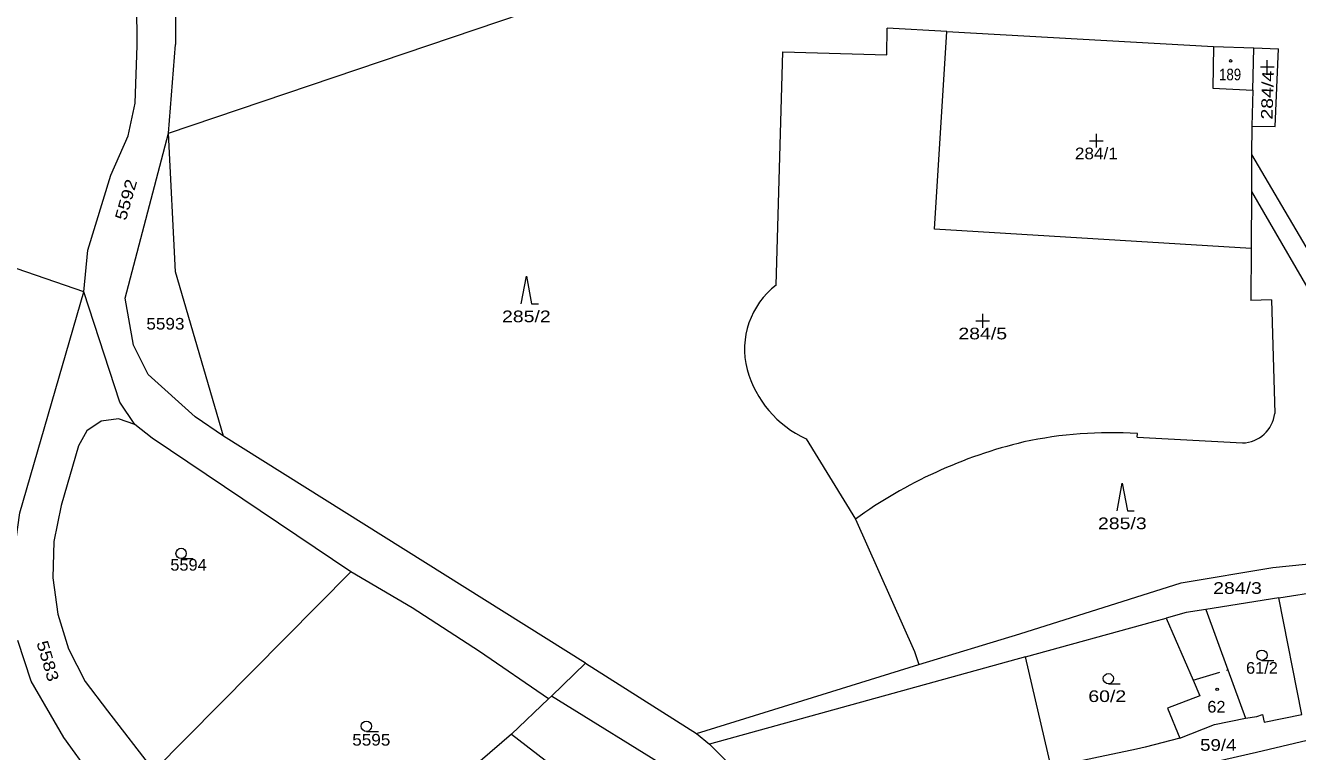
# Model space of a CAD drawing. Extents: x -590528 to -586543, y -1119609 to -1116685.
# Drawn here: x -589346.9 to -589161.2, y -1118438.6 to -1118332.6 of the extents above; entities that cross this region are included whole.
import ezdxf
from ezdxf.enums import TextEntityAlignment as Align

# ---------------------------------------------------------------- set-up
doc = ezdxf.new("R2010")
doc.units = 0
doc.header["$LTSCALE"] = 0.68
doc.linetypes.add('LONG_DASHED', pattern=[7.5, 6, -1.5])
for name, color, linetype, lineweight in [('1', 7, 'Continuous', 13), ('2', 7, 'LONG_DASHED', 13), ('3', 7, 'Continuous', 13), ('6', 7, 'Continuous', 13)]:
    doc.layers.add(name, color=color, linetype=linetype, lineweight=lineweight)

msp = doc.modelspace()

# ---------------------------------------------------------------- linework, layer by layer
at = {"layer": '1'}
for p, q in [((-589326.04, -1118348.34), (-589245.69, -1118321.18)), ((-589221.18, -1118336.9), (-589221.12, -1118333.05)), ((-589212.42, -1118333.53), (-589221.12, -1118333.05)), ((-589212.42, -1118333.53), (-589173.46, -1118335.7)), ((-589326.04, -1118348.34), (-589325.05, -1118335.4)), ((-589237.33, -1118370.53), (-589236.34, -1118336.48)), ((-589236.34, -1118336.48), (-589221.18, -1118336.9)), ((-589173.46, -1118335.7), (-589173.55, -1118341.78)), ((-589167.7, -1118342.06), (-589167.58, -1118335.91)), ((-589173.55, -1118341.78), (-589167.7, -1118342.06)), ((-589167.7, -1118342.06), (-589167.88, -1118347.35)), ((-589338.39, -1118371.5), (-589403.04, -1118349.36)), ((-589332.36, -1118372.41), (-589326.04, -1118348.34)), ((-589325.03, -1118368.61), (-589326.04, -1118348.34)), ((-589167.9, -1118351.48), (-589148.72, -1118384.16)), ((-589167.93, -1118356.86), (-589150.27, -1118387.26)), ((-589318.03, -1118392.58), (-589325.03, -1118368.61)), ((-589165.02, -1118372.65), (-589168.02, -1118372.79)), ((-589165.02, -1118372.65), (-589164.53, -1118389.24)), ((-589318.03, -1118392.58), (-589322.16, -1118389.75)), ((-589184.6, -1118392.69), (-589184.58, -1118392.17)), ((-589299.45, -1118412.34), (-589328.45, -1118392.88)), ((-589265.17, -1118425.71), (-589318.03, -1118392.58)), ((-589184.6, -1118392.69), (-589169.25, -1118393.56)), ((-589328.21, -1118441.4), (-589299.45, -1118412.34)), ((-589200.94, -1118424.78), (-589182.2, -1118419.61)), ((-589182.2, -1118419.61), (-589180.39, -1118419.11)), ((-589216.49, -1118425.91), (-589201.73, -1118421.4)), ((-589270.59, -1118430.92), (-589280.62, -1118423.97)), ((-589217.13, -1118423.98), (-589216.49, -1118425.91)), ((-589270.14, -1118430.49), (-589265.17, -1118425.71)), ((-589265.17, -1118425.71), (-589248.97, -1118435.94)), ((-589248.97, -1118435.94), (-589216.49, -1118425.91)), ((-589200.94, -1118424.78), (-589247.08, -1118437.51)), ((-589197.19, -1118440.86), (-589200.94, -1118424.78)), ((-589275.98, -1118436.06), (-589270.59, -1118430.92)), ((-589270.59, -1118430.92), (-589270.14, -1118430.49)), ((-589251.89, -1118441.81), (-589270.14, -1118430.49)), ((-589275.98, -1118436.06), (-589292.08, -1118449.9)), ((-589248.97, -1118435.94), (-589247.08, -1118437.51))]:
    msp.add_line(p, q, dxfattribs=at)
for points in [[(-589324.34, -1118242.06), (-589284.26, -1118252.28), (-589283.44, -1118293.46), (-589306.78, -1118295.36), (-589324.77, -1118296.83), (-589324.8, -1118300.73), (-589324.91, -1118315.62), (-589325.05, -1118335.4)], [(-589338.39, -1118371.5), (-589337.84, -1118365.42), (-589334.45, -1118354.46), (-589331.95, -1118348.76), (-589330.94, -1118343.98), (-589330.65, -1118335.55), (-589330.68, -1118329.38)], [(-589167.98, -1118365.19), (-589214.19, -1118362.36), (-589212.42, -1118333.53)], [(-589173.46, -1118335.7), (-589167.58, -1118335.91), (-589163.96, -1118336.03)], [(-589167.88, -1118347.35), (-589164.44, -1118347.37), (-589163.96, -1118336.03)], [(-589167.88, -1118347.35), (-589167.9, -1118351.48), (-589167.93, -1118356.86), (-589167.98, -1118365.19), (-589168.02, -1118372.79)], [(-589382.59, -1118398.58), (-589371.5, -1118401.89), (-589356.23, -1118406.75), (-589348.52, -1118409.33), (-589347.77, -1118403.74), (-589338.39, -1118371.5)], [(-589330.98, -1118390.87), (-589333.18, -1118387.62), (-589338.39, -1118371.5)], [(-589322.16, -1118389.75), (-589329.04, -1118383.57), (-589331.18, -1118379.27), (-589332.36, -1118372.41)], [(-589328.45, -1118392.88), (-589330.98, -1118390.87), (-589333.36, -1118390.04), (-589335.87, -1118390.37), (-589337.96, -1118391.78), (-589339.21, -1118393.98), (-589341.74, -1118402.69), (-589342.79, -1118407.92), (-589342.96, -1118413.25), (-589342.23, -1118418.53), (-589340.63, -1118423.61)], [(-589232.96, -1118392.96), (-589225.76, -1118404.68), (-589217.13, -1118423.98)], [(-589374.32, -1118404.86), (-589380.45, -1118462.92), (-589374.76, -1118462.64), (-589367.9, -1118459.92), (-589356.04, -1118453.27), (-589344.63, -1118446.86), (-589337.38, -1118442.01), (-589341.33, -1118436.52), (-589346.1, -1118428.33), (-589348.05, -1118422.4)], [(-589201.73, -1118421.4), (-589178.17, -1118413.95), (-589164.81, -1118411.74), (-589141.45, -1118409.35)], [(-589280.62, -1118423.97), (-589290.49, -1118417.6), (-589299.45, -1118412.34)], [(-589163.94, -1118416.17), (-589174.61, -1118417.86), (-589177.47, -1118418.31), (-589180.39, -1118419.11)], [(-589178.39, -1118436.62), (-589173.34, -1118434.64), (-589168.8, -1118433.71), (-589167.16, -1118433.45), (-589166.32, -1118433.19), (-589166.08, -1118434.28), (-589160.56, -1118433.2), (-589163.94, -1118416.17)], [(-589163.94, -1118416.17), (-589157.76, -1118415.19), (-589148.57, -1118424.88)], [(-589174.61, -1118417.86), (-589171.39, -1118426.64), (-589168.8, -1118433.71)], [(-589180.39, -1118419.11), (-589176.44, -1118428.18), (-589175.45, -1118430.45), (-589180.19, -1118432.28), (-589178.39, -1118436.62), (-589183.44, -1118437.97), (-589184.7, -1118438.23), (-589197.19, -1118440.86)], [(-589340.63, -1118423.61), (-589338.2, -1118428.36), (-589334.98, -1118432.65), (-589328.21, -1118441.4), (-589325.78, -1118444.54), (-589322.29, -1118448.62)], [(-589199.68, -1118448.07), (-589194.46, -1118445.28), (-589188.61, -1118443.7), (-589176.77, -1118440.88), (-589167.18, -1118438.67), (-589159.81, -1118436.94), (-589154.47, -1118435.78), (-589147.85, -1118434.23), (-589145.26, -1118446.55), (-589151.66, -1118448.03), (-589156.96, -1118449.29), (-589164.32, -1118451), (-589166.12, -1118451.49)], [(-589275.98, -1118436.06), (-589265.05, -1118444.46), (-589262.78, -1118446.21)], [(-589247.08, -1118437.51), (-589221.83, -1118462.82), (-589205.62, -1118461.09)]]:
    msp.add_lwpolyline(points, dxfattribs=at)
for centre, radius, start, end in [((-589230.1545, -1118379.8912), 11.795, 127.47081, 194.37743), ((-589226.2424, -1118378.5155), 15.9301, 195.67687, 245.05876), ((-589169.3468, -1118388.7157), 4.8452, 271.14464, 353.78824), ((-589188.3272, -1118453.7384), 61.6824, 86.51712, 102.02686), ((-589184.8908, -1118461.3765), 69.8912, 103.47757, 125.78561)]:
    msp.add_arc(centre, radius, start, end, dxfattribs=at)
at = {"layer": '2'}
msp.add_line((-589176.44, -1118428.18), (-589171.39, -1118426.64), dxfattribs=at)
at = {"layer": '6'}
for p, q in [((-589165.62, -1118339.69), (-589165.62, -1118337.69)), ((-589166.62, -1118338.69), (-589164.62, -1118338.69)), ((-589191.57, -1118349.46), (-589189.57, -1118349.46)), ((-589190.57, -1118350.46), (-589190.57, -1118348.46)), ((-589208.16, -1118375.74), (-589206.16, -1118375.74)), ((-589207.16, -1118376.74), (-589207.16, -1118374.74)), ((-589324.21, -1118410.42), (-589322.46, -1118410.42)), ((-589166.39, -1118425.28), (-589164.64, -1118425.28)), ((-589188.82, -1118428.7), (-589187.07, -1118428.7)), ((-589297.16, -1118435.65), (-589295.41, -1118435.65))]:
    msp.add_line(p, q, dxfattribs=at)
for points in [[(-589274.55, -1118373.24), (-589273.8, -1118369.24), (-589273.05, -1118373.24), (-589272.05, -1118373.24)], [(-589187.53, -1118403.44), (-589186.78, -1118399.44), (-589186.03, -1118403.44), (-589185.03, -1118403.44)]]:
    msp.add_lwpolyline(points, dxfattribs=at)
for centre, radius in [((-589170.9702, -1118337.8004), 0.175), ((-589324.21, -1118409.67), 0.75), ((-589166.39, -1118424.53), 0.75), ((-589188.82, -1118427.95), 0.75), ((-589172.9302, -1118429.4904), 0.175), ((-589297.16, -1118434.9), 0.75)]:
    msp.add_circle(centre, radius, dxfattribs=at)

# ---------------------------------------------------------------- texts
at = {"layer": '3'}
for s, width, p in [('189', 0.85, (-589171.0405, -1118340.64)), ('284/1', 1.1, (-589190.571, -1118352.16)), ('285/2', 1.25, (-589273.8, -1118375.94)), ('284/5', 1.25, (-589207.16, -1118378.44)), ('285/3', 1.25, (-589186.78, -1118406.14)), ('284/3', 1.25, (-589169.9605, -1118415.58)), ('61/2', 1.05, (-589166.39, -1118427.23)), ('60/2', 1.25, (-589188.98, -1118431.36)), ('62', 1.05, (-589173.041, -1118432.9)), ('59/4', 1.2, (-589172.7705, -1118438.48))]:
    msp.add_text(s, height=1.7, dxfattribs=dict(at, width=width)).set_placement(p, align=Align.CENTER)
at = {"layer": '3', "width": 1.25}
msp.add_text('284/4', height=1.7, rotation=88.293, dxfattribs=at).set_placement((-589164.749, -1118342.8348), align=Align.CENTER)
at = {"layer": '3', "width": 1.2}
for s, rotation, p in [('5592', 74.083, (-589332.275, -1118361.202)), ('5583', 286.479, (-589345.343, -1118422.708))]:
    msp.add_text(s, height=1.7, rotation=rotation, dxfattribs=at).set_placement(p)
at = {"layer": '3'}
for s, width, p in [('5593', 1.1, (-589329.283, -1118377.01)), ('5594', 1.05, (-589325.783, -1118412.19)), ('5595', 1.1, (-589299.223, -1118437.72))]:
    msp.add_text(s, height=1.7, dxfattribs=dict(at, width=width)).set_placement(p)

doc.saveas('drawing.dxf')
